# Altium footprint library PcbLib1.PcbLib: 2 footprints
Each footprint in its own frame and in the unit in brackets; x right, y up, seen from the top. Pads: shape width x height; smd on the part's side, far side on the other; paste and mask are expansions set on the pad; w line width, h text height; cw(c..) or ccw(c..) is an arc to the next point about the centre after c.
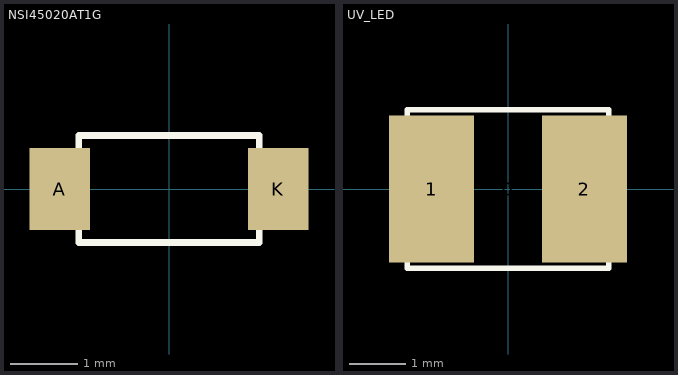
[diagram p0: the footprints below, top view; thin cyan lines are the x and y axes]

## NSI45020AT1G [mm]
pads (2):
  rect 0.91x1.22 smd: A(-1.635,0) K(1.635,0)
Top Overlay:
  lines w0.1: -1.35,-0.8 -1.35,0.8 1.35,0.8 1.35,-0.8 -1.35,-0.8

## UV_LED [mm]
pads (3):
  rect 1x1 on Top Overlay: 0(0,0)
  rect 1.5x2.6 smd: 1(-1.35,0) 2(1.35,0)
Top Overlay:
  lines w0.1: -1.778,-1.4 1.778,-1.4 1.778,1.4 -1.778,1.4 -1.778,-1.4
